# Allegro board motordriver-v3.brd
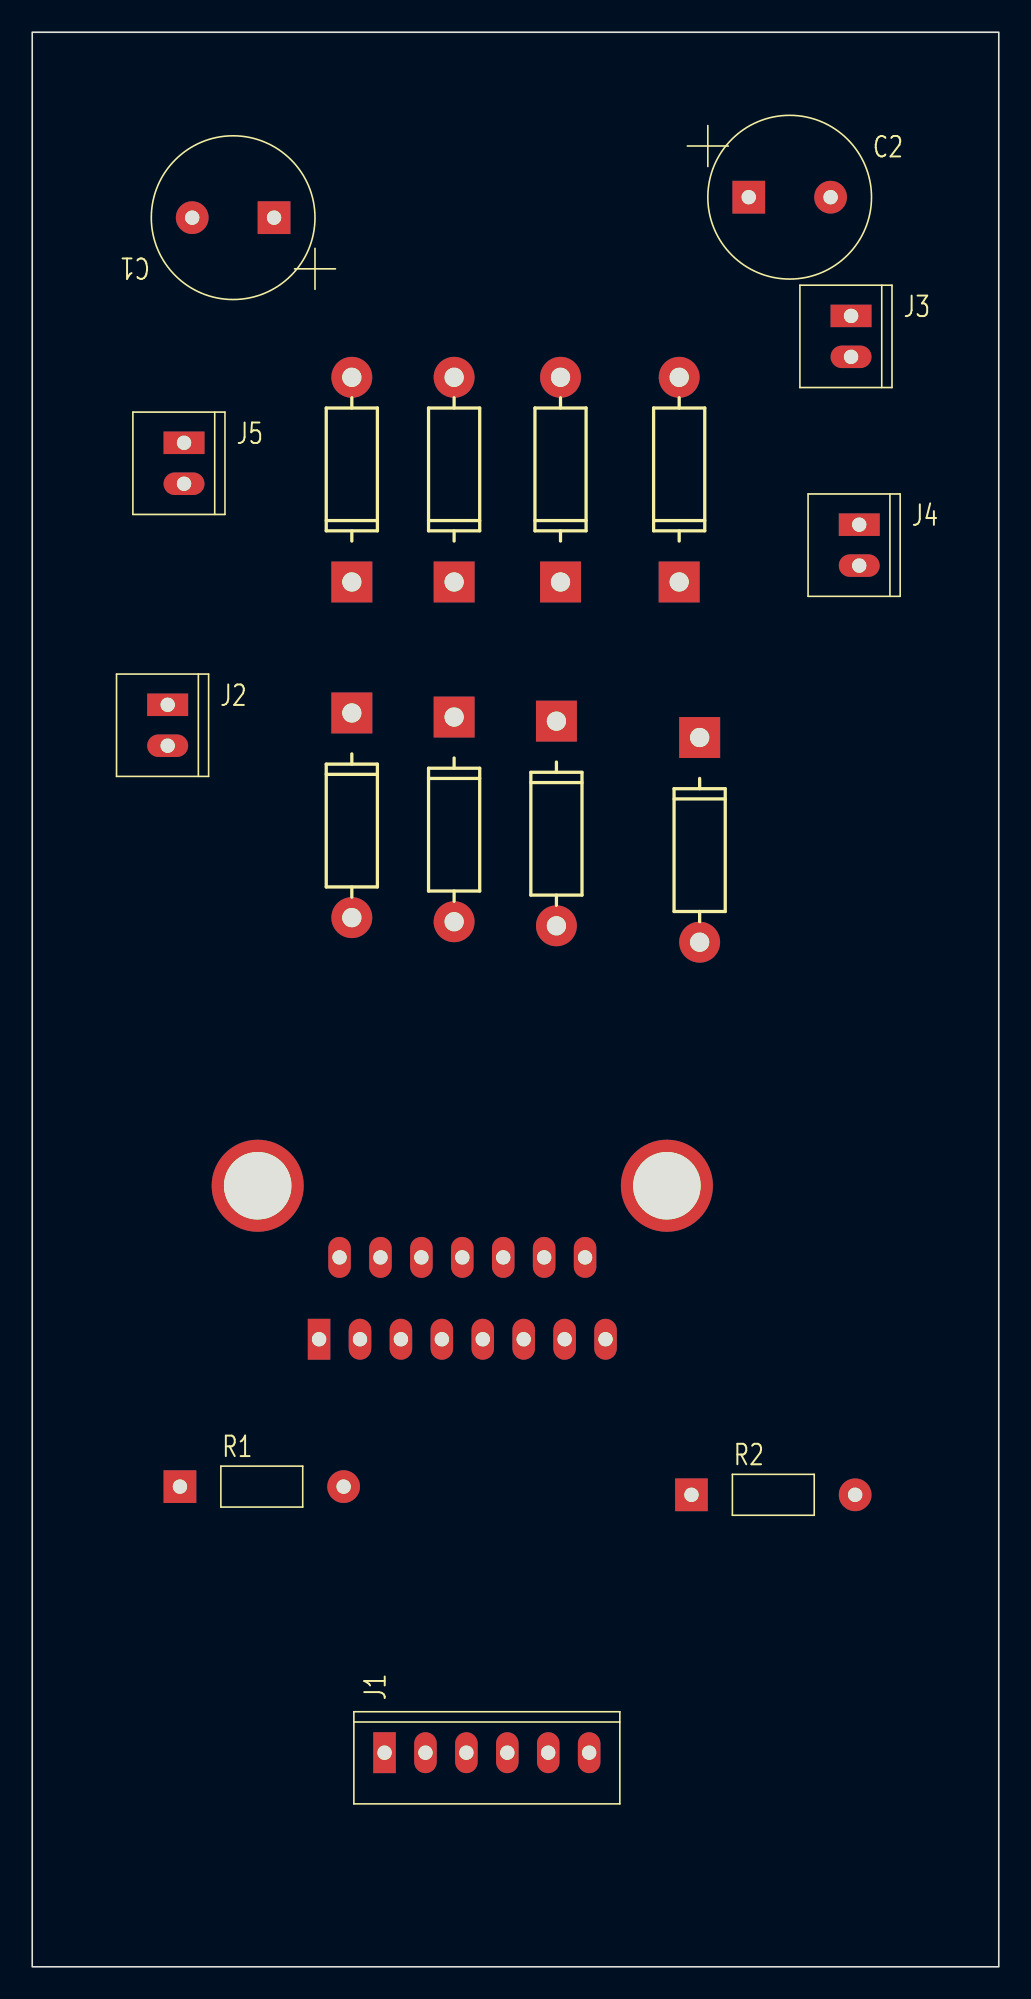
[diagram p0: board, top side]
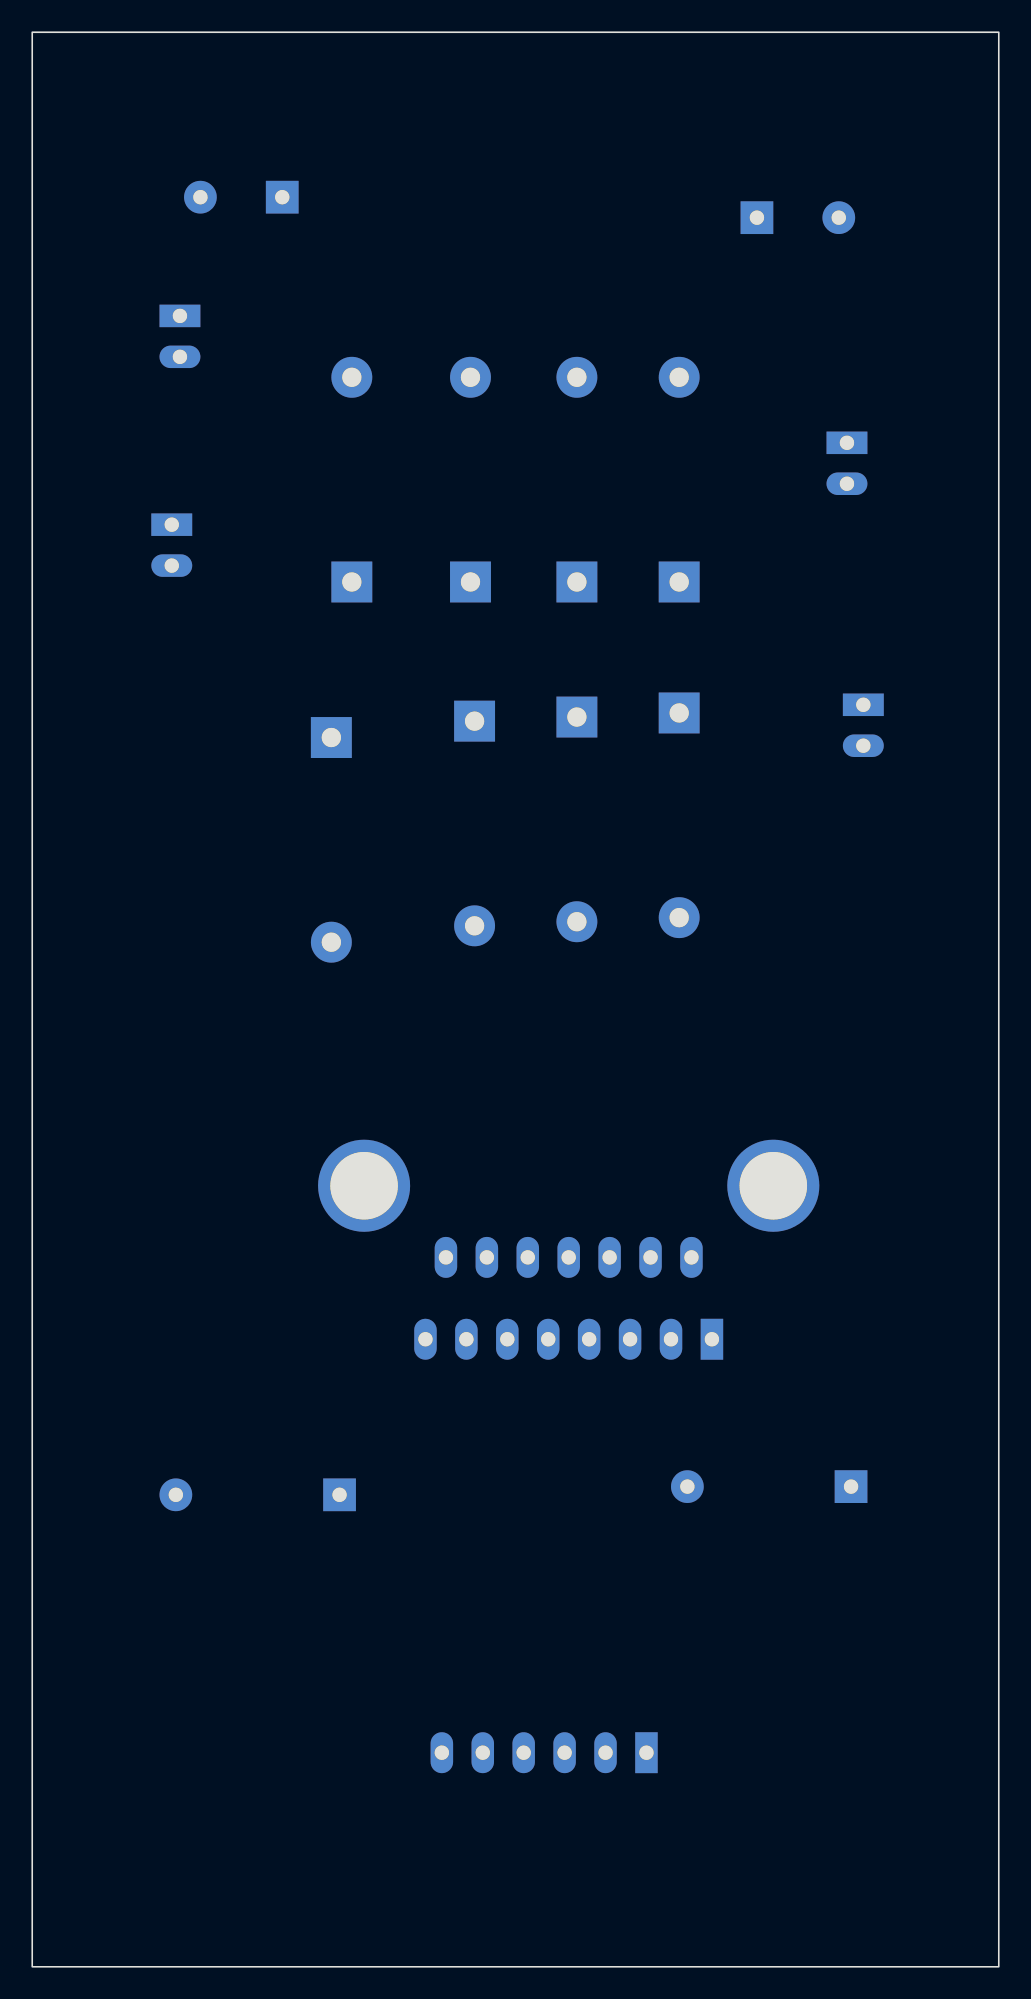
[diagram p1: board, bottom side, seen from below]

Outline 59.99 x 120.04 mm; copper layers: TOP, BOTTOM. Coordinates in mm from the lower left corner of the outline.
Outline path: rectangle 0,0 59.99,120.04

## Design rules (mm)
constraint set DEFAULT: min track width 0.762

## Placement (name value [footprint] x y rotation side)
C1  CAP POL  [GU-CAPCYL200]  15.01 108.53 180 top
C2  CAP POL  [GU-CAPCYL200]  44.48 109.8 0 top
D1  DIODE  [GU-1N4001]  40.16 85.93 90 top
D2  DIODE  [GU-1N4001]  41.43 76.28 270 top
D3  DIODE  [GU-1N4001]  32.79 85.93 90 top
D4  DIODE  [GU-1N4001]  32.54 77.29 270 top
D5  DIODE  [GU-1N4001]  26.19 85.93 90 top
D6  DIODE  [GU-1N4001]  26.19 77.55 270 top
D7  DIODE  [GU-1N4001]  19.84 85.93 90 top
D8  DIODE  [GU-1N4001]  19.84 77.8 270 top
J1  CON6  [GU-MOLEX6]  21.87 13.28 90 top
J2  CON2  [GU-MOLEX2]  8.41 78.31 0 top
J3  CON2  [GU-MOLEX2]  50.83 102.44 0 top
J4  CON2  [GU-MOLEX2]  51.33 89.48 0 top
J5  CON2  [GU-MOLEX2]  9.42 94.56 0 top
R1  R  [GU-RC400]  9.17 29.79 0 top
R2  R  [GU-RC400]  40.92 29.29 0 top
U1  L298/MUTIV  [GU-L298-HSINK2]  17.81 38.94 0 top

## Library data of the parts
C1 C2 = CAP POL
D1-D8 = DIODE
J1 = CON6
J2-J5 = CON2
R1 R2 = R
U1 = L298/MUTIV_0

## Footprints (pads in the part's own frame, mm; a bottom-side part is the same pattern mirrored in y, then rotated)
GU-1N4001
  round 2.54 hole 1.194: 1(12.7,0)
  rect 2.54x2.54 hole 1.194: 2(0,0)
GU-CAPCYL200
  rect 2.032x2.032 hole 0.889: 1(0,0)
  round 2.032 hole 0.889: 2(5.08,0)
GU-L298-HSINK2
  round 5.715 hole 4.191 unplated: (-3.81,9.525) (21.59,9.525)
  rect 1.397x2.54 hole 0.889: 1(0,0)
  oval 1.397x2.54 hole 0.889: 2(1.27,5.08) 3(2.54,0) 4(3.81,5.08) 5(5.08,0) 6(6.35,5.08) 7(7.62,0) 8(8.89,5.08) 9(10.16,0) 10(11.43,5.08) 11(12.7,0) 12(13.97,5.08) 13(15.24,0) 14(16.51,5.08) 15(17.78,0)
GU-MOLEX2
  rect 2.54x1.397 hole 0.889: 1(0,0)
  oval 2.54x1.397 hole 0.889: 2(0,-2.54)
GU-MOLEX6
  rect 2.54x1.397 hole 0.889: 1(0,0)
  oval 2.54x1.397 hole 0.889: 2(0,-2.54) 3(0,-5.08) 4(0,-7.62) 5(0,-10.16) 6(0,-12.7)
GU-RC400
  rect 2.032x2.032 hole 0.889: 1(0,0)
  round 2.032 hole 0.889: 2(10.16,0)

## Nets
12V: C2.1 D1.1(K) D3.1(K) D5.1(K) D7.1(K) J3.2 U1.4
GND: C1.2 C2.2 D2.2 D4.2 D6.2 D8.2 J2.2 J3.1 R1.2 R2.2 U1.8
ENA: J1.5 U1.6
ENB: J1.6 U1.11
IN1: J1.1 U1.5
IN2: J1.2 U1.7
IN3: J1.3 U1.10
IN4: J1.4 U1.12
OUT1: D1.2 D2.1(K) J4.1 U1.2
OUT2: D3.2 D4.1(K) J4.2 U1.3
OUT3: D5.2 D6.1(K) J5.1 U1.13
OUT4: D7.2 D8.1(K) J5.2 U1.14
N00290: C1.1 J2.1 U1.9(VSS)
N00456: R1.1 U1.1
N00460: R2.1 U1.15
